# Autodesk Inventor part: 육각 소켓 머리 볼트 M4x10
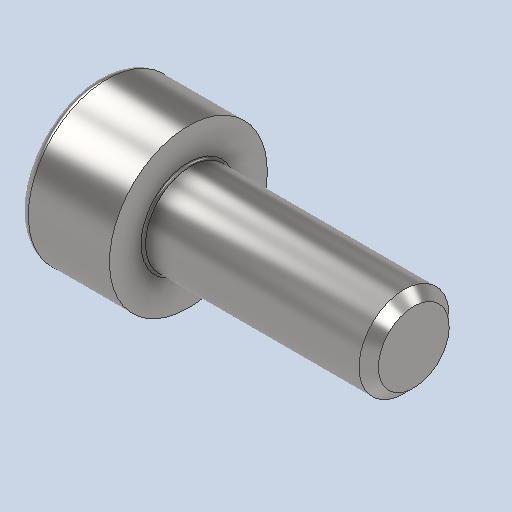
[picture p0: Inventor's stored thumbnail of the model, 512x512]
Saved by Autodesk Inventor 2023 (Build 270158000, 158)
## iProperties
Created: 2024-09
Part Number: 육각 소켓 머리 볼트 M4x10
Material: 강철, 연강
Description: 6각머리 태핑 나사
Document SubType Name: Modeling
Designer: home
Density: 7.85 g/cm^3
Appearance: 기본값
Author: jhkim
Sending System: Autodesk Inventor 2025
Preprocessor: ST-DEVELOPER v20
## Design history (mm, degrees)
feature "Solid1"
node "솔리드1"
